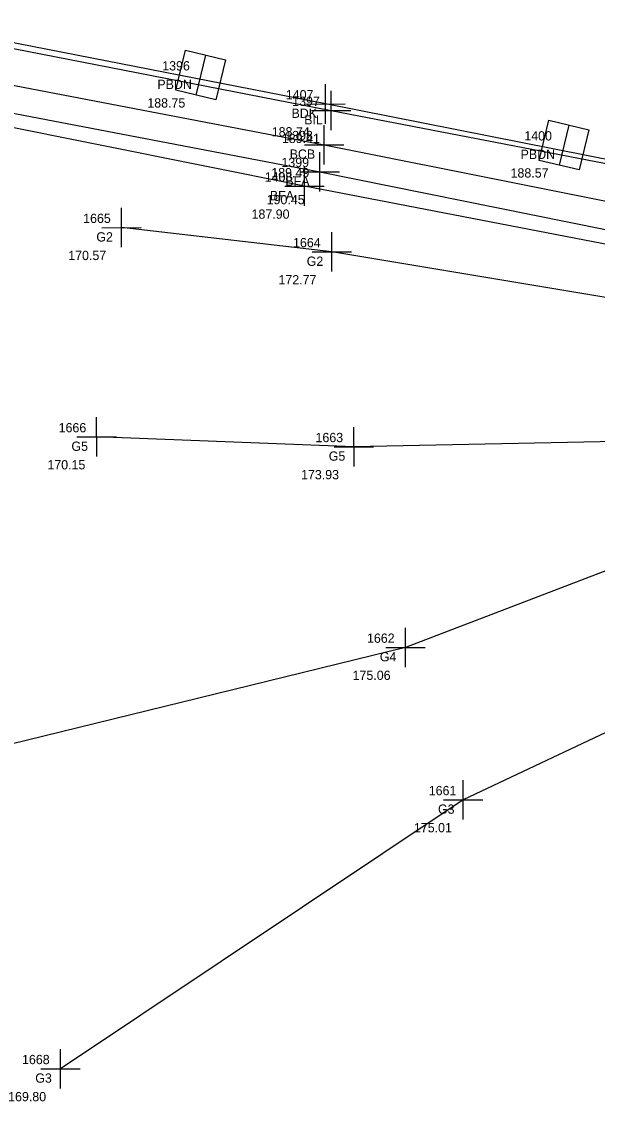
# Model space of a CAD drawing. Extents: x 1157913 to 1159198, y 600595 to 601244.
# Drawn here: x 1158682.74 to 1158701.34, y 600851.11 to 600886.03 of the extents above; entities that cross this region are included whole.
import ezdxf

# ---------------------------------------------------------------- set-up
doc = ezdxf.new("R2010")
doc.units = 0
for name, color, linetype in [('Default', 7, 'Continuous'), ('S_Bridge_Curb', 7, 'Continuous'), ('S_Bridge_Deck', 7, 'Continuous'), ('S_Bridge_Downspout', 7, 'Continuous'), ('S_Bridge_Fascia', 7, 'Continuous'), ('S_Bridge_Rail', 7, 'Continuous'), ('S_Field_Code', 7, 'Continuous'), ('S_Ground_Elevation', 7, 'Continuous'), ('S_Point_Elevation', 7, 'Continuous'), ('S_Point_Name', 7, 'Continuous'), ('S_Survey_Shot', 7, 'Continuous')]:
    doc.layers.add(name, color=color, linetype=linetype)

msp = doc.modelspace()

# ---------------------------------------------------------------- linework, layer by layer
at = {"layer": 'Default'}
for p, q in [((1158688.526, 600884.301), (1158688.526, 600884.301)), ((1158700.263, 600882.037), (1158700.263, 600882.037))]:
    msp.add_line(p, q, dxfattribs=at)
at = {"layer": 'S_Bridge_Curb'}
msp.add_lwpolyline([(1158478.174, 600924.072), (1158503.549, 600919.114), (1158527.549, 600914.557), (1158551.032, 600910.063), (1158574.638, 600905.207), (1158597.984, 600900.814), (1158621.679, 600896.121), (1158645.574, 600891.298), (1158668.721, 600886.601), (1158692.515, 600882.046), (1158718.247, 600876.909)], dxfattribs=at)
at = {"layer": 'S_Bridge_Deck'}
msp.add_lwpolyline([(1158483.154, 600948.642), (1158508.91, 600943.661), (1158532.625, 600939.025), (1158556.015, 600934.45), (1158579.602, 600929.788), (1158603.216, 600925.172), (1158626.871, 600920.52), (1158650.274, 600915.846), (1158673.938, 600911.396), (1158697.587, 600906.778), (1158722.887, 600901.626), (1158720.511, 600890.631), (1158717.86, 600878.361), (1158692.562, 600883.367), (1158669.405, 600887.913), (1158645.122, 600892.525), (1158622.108, 600897.299), (1158598.216, 600901.842), (1158574.819, 600906.519), (1158551.011, 600911.144), (1158527.523, 600915.567), (1158503.608, 600920.228), (1158478.738, 600925.244), (1158480.987, 600937.158)], close=True, dxfattribs=at)
at = {"layer": 'S_Bridge_Downspout'}
for p, q in [((1158688.682, 600884.949), (1158688.371, 600883.653)), ((1158700.419, 600882.685), (1158700.108, 600881.389))]:
    msp.add_line(p, q, dxfattribs=at)
for points in [[(1158688.034, 600885.105), (1158689.33, 600884.794), (1158689.019, 600883.497), (1158687.722, 600883.809)], [(1158699.771, 600882.841), (1158701.067, 600882.529), (1158700.756, 600881.233), (1158699.459, 600881.544)]]:
    msp.add_lwpolyline(points, close=True, dxfattribs=at)
at = {"layer": 'S_Bridge_Fascia'}
msp.add_lwpolyline([(1158477.27, 600923.329), (1158503.529, 600918.158), (1158527.207, 600913.702), (1158550.741, 600909.047), (1158574.385, 600904.349), (1158597.753, 600899.594), (1158621.448, 600895.033), (1158645.16, 600890.284), (1158668.539, 600885.727), (1158692.378, 600881.174), (1158718.73, 600875.851), (1158718.692, 600875.535), (1158691.877, 600880.706), (1158668.575, 600885.39), (1158645.229, 600889.981), (1158621.38, 600894.578), (1158597.772, 600899.255), (1158574.312, 600903.82), (1158550.668, 600908.561), (1158526.887, 600913.271), (1158503.449, 600917.667), (1158477.221, 600922.938)], close=True, dxfattribs=at)
at = {"layer": 'S_Bridge_Rail'}
msp.add_lwpolyline([(1158478.595, 600925.242), (1158503.898, 600920.176), (1158527.611, 600915.661), (1158551.296, 600911.071), (1158574.9, 600906.289), (1158598.35, 600901.85), (1158621.733, 600897.102), (1158645.532, 600892.49), (1158669.112, 600887.777), (1158692.742, 600883.154), (1158718.452, 600878.194)], dxfattribs=at)
at = {"layer": 'S_Ground_Elevation'}
for points in [[(1158729.41, 600874.357), (1158728.971, 600873.551), (1158724.742, 600874.099), (1158719.073, 600874.59), (1158713.519, 600875.129), (1158692.766, 600878.583), (1158685.971, 600879.369)], [(1158725.359, 600869.343), (1158717.55, 600871.41), (1158713.121, 600872.674), (1158695.143, 600865.793), (1158680.676, 600862.247)], [(1158713.121, 600872.674), (1158693.478, 600872.281), (1158685.164, 600872.6)], [(1158725.784, 600865.556), (1158720.366, 600866.316), (1158710.3, 600868.801), (1158703.347, 600863.862), (1158697.007, 600860.865), (1158683.996, 600852.168)]]:
    msp.add_lwpolyline(points, dxfattribs=at)
at = {"layer": 'S_Survey_Shot'}
for p, q in [((1158692.563, 600882.73), (1158692.56, 600884.003)), ((1158692.743, 600882.518), (1158692.741, 600883.79)), ((1158691.925, 600883.365), (1158693.198, 600883.368)), ((1158692.562, 600883.367), (1158692.562, 600883.367)), ((1158692.106, 600883.153), (1158693.378, 600883.155)), ((1158692.742, 600883.154), (1158692.742, 600883.154)), ((1158692.517, 600881.41), (1158692.514, 600882.682)), ((1158691.879, 600882.045), (1158693.152, 600882.047)), ((1158692.515, 600882.046), (1158692.515, 600882.046)), ((1158692.379, 600880.538), (1158692.376, 600881.81)), ((1158691.879, 600880.069), (1158691.876, 600881.342)), ((1158691.741, 600881.173), (1158693.014, 600881.175)), ((1158692.378, 600881.174), (1158692.378, 600881.174)), ((1158691.241, 600880.704), (1158692.513, 600880.707)), ((1158691.877, 600880.706), (1158691.877, 600880.706)), ((1158685.972, 600878.732), (1158685.969, 600880.005)), ((1158685.335, 600879.367), (1158686.607, 600879.37)), ((1158685.971, 600879.369), (1158685.971, 600879.369)), ((1158692.768, 600877.947), (1158692.765, 600879.219)), ((1158692.13, 600878.581), (1158693.403, 600878.584)), ((1158692.766, 600878.583), (1158692.766, 600878.583)), ((1158685.166, 600871.964), (1158685.163, 600873.237)), ((1158693.48, 600871.645), (1158693.477, 600872.918)), ((1158684.528, 600872.599), (1158685.801, 600872.602)), ((1158685.164, 600872.6), (1158685.164, 600872.6)), ((1158692.842, 600872.28), (1158694.115, 600872.283)), ((1158693.478, 600872.281), (1158693.478, 600872.281)), ((1158695.144, 600865.157), (1158695.141, 600866.429)), ((1158694.506, 600865.792), (1158695.779, 600865.794)), ((1158695.143, 600865.793), (1158695.143, 600865.793)), ((1158697.009, 600860.229), (1158697.006, 600861.501)), ((1158696.371, 600860.864), (1158697.644, 600860.867)), ((1158697.007, 600860.865), (1158697.007, 600860.865)), ((1158683.998, 600851.532), (1158683.995, 600852.804)), ((1158683.36, 600852.167), (1158684.633, 600852.169)), ((1158683.996, 600852.168), (1158683.996, 600852.168))]:
    msp.add_line(p, q, dxfattribs=at)

# ---------------------------------------------------------------- texts
at = {"layer": 'S_Field_Code'}
for s, p in [('PBDN', (1158687.126, 600883.851)), ('BDK', (1158691.461, 600882.917)), ('BIL', (1158691.871, 600882.704)), ('BCB', (1158691.401, 600881.596)), ('PBDN', (1158698.863, 600881.587)), ('BFA', (1158691.261, 600880.724)), ('BFA', (1158690.76, 600880.256)), ('G2', (1158685.156, 600878.919)), ('G2', (1158691.952, 600878.133)), ('G5', (1158684.35, 600872.15)), ('G5', (1158692.664, 600871.831)), ('G4', (1158694.314, 600865.343)), ('G3', (1158696.193, 600860.415)), ('G3', (1158683.181, 600851.718))]:
    msp.add_text(s, height=0.3, dxfattribs=at).set_placement(p)
at = {"layer": 'S_Point_Elevation'}
for s, p in [('188.75', (1158686.802, 600883.251)), ('188.74', (1158690.823, 600882.317)), ('189.41', (1158691.15, 600882.104)), ('189.49', (1158690.808, 600880.996)), ('188.57', (1158698.539, 600880.987)), ('190.45', (1158690.658, 600880.124)), ('187.90', (1158690.17, 600879.656)), ('170.57', (1158684.247, 600878.319)), ('172.77', (1158691.038, 600877.533)), ('170.15', (1158683.573, 600871.55)), ('173.93', (1158691.769, 600871.231)), ('175.06', (1158693.435, 600864.743)), ('175.01', (1158695.416, 600859.815)), ('169.80', (1158682.305, 600851.118))]:
    msp.add_text(s, height=0.3, dxfattribs=at).set_placement(p)
at = {"layer": 'S_Point_Name'}
for s, p in [('1396', (1158687.284, 600884.451)), ('1407', (1158691.277, 600883.517)), ('1397', (1158691.483, 600883.304)), ('1398', (1158691.259, 600882.196)), ('1400', (1158698.983, 600882.187)), ('1399', (1158691.135, 600881.324)), ('1408', (1158690.595, 600880.856)), ('1665', (1158684.729, 600879.519)), ('1664', (1158691.51, 600878.733)), ('1666', (1158683.936, 600872.75)), ('1663', (1158692.236, 600872.431)), ('1662', (1158693.9, 600865.943)), ('1661', (1158695.895, 600861.015)), ('1668', (1158682.754, 600852.318))]:
    msp.add_text(s, height=0.3, dxfattribs=at).set_placement(p)

doc.saveas('drawing.dxf')
